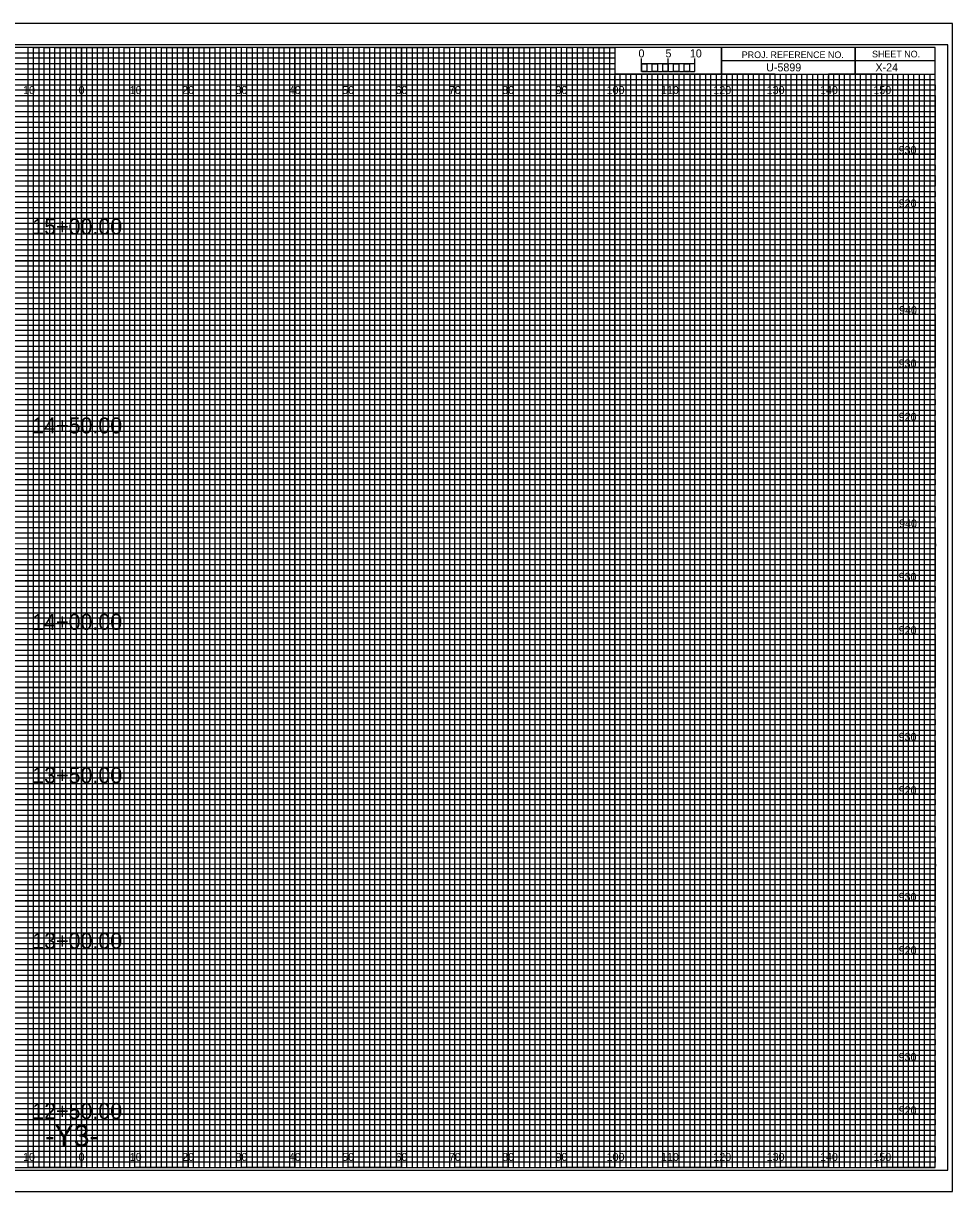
# Model space of a CAD drawing. Extents: x -13 to 323, y 216 to 434.
# Drawn here: x 149.1 to 323.3, y 215.5 to 434.5 of the extents above; entities that cross this region are included whole.
import ezdxf

# ---------------------------------------------------------------- set-up
doc = ezdxf.new("R2010")
doc.units = 0
for name, color, linetype in [('Prop XS Alignment Label', 7, 'Continuous'), ('Prop XS Bar Scale Labels', 7, 'Continuous'), ('Prop XS Elevation Labels', 7, 'Continuous'), ('Prop XS Label Text', 7, 'Continuous'), ('Prop XS Project Number', 7, 'Continuous'), ('Prop XS Shear Point Element', 7, 'Continuous'), ('Prop XS Shear Point Label', 7, 'Continuous'), ('Prop XS Sheet Number', 7, 'Continuous'), ('Prop XS Station Labels', 7, 'Continuous'), ('Scratch_Level_1', 7, 'Continuous'), ('Scratch_Level_4', 7, 'Continuous'), ('Sheet Cross Section Grid Minor 2 CELL', 7, 'Continuous'), ('Sheet Cross Section Scale CELL', 7, 'Continuous'), ('Sheet Cutting Line CELL', 7, 'Continuous'), ('Sheet DOT Grid CELL', 7, 'Continuous'), ('Sheet Plot Border Inside CELL', 7, 'Continuous'), ('Sheet Plot Border Outside CELL', 7, 'Continuous')]:
    doc.layers.add(name, color=color, linetype=linetype)

msp = doc.modelspace()

# ---------------------------------------------------------------- linework, layer by layer
at = {"layer": 'Prop XS Label Text'}
for points in [[(145, 220), (155, 220), (155, 430), (165, 430), (165, 220), (175, 220), (175, 430), (185, 430), (185, 220), (195, 220), (195, 430), (205, 430), (205, 220), (215, 220), (215, 430), (225, 430), (225, 220), (235, 220), (235, 430), (245, 430), (245, 220), (255, 220), (255, 430), (259.93, 430), (260, 430), (260, 425), (264.99, 425), (264.99, 220), (275, 220), (275, 425), (285, 425), (285, 220), (295, 220), (295, 425), (305, 425), (305, 220), (315, 220), (315, 425)], [(0, 425), (275, 425)], [(0, 405), (320, 405), (320, 415), (0, 415)], [(0, 385), (320, 385), (320, 395), (0, 395)], [(0, 365), (320, 365), (320, 375), (0, 375)], [(0, 345), (320, 345), (320, 355), (0, 355)], [(0, 325), (320, 325), (320, 335), (0, 335)], [(0, 305), (320, 305), (320, 315), (0, 315)], [(0, 285), (320, 285), (320, 295), (0, 295)], [(0, 265), (320, 265), (320, 275), (0, 275)], [(0, 245), (320, 245), (320, 255), (0, 255)], [(0, 225), (320, 225), (320, 235), (0, 235)]]:
    msp.add_lwpolyline(points, dxfattribs=at)
at = {"layer": 'Prop XS Shear Point Element'}
for p, q in [((305, 430), (305, 425)), ((305, 425), (305, 430)), ((280, 427.5), (280, 425)), ((320, 427.49), (280, 427.49)), ((280, 425), (320, 425))]:
    msp.add_line(p, q, dxfattribs=at)
for points in [[(320, 430), (0, 430), (0, 220), (320, 220)], [(280, 430), (260, 430), (260, 425.03), (280, 425.03)], [(320, 430), (280, 430), (280, 425), (320, 425)]]:
    msp.add_lwpolyline(points, close=True, dxfattribs=at)
at = {"layer": 'Prop XS Shear Point Label'}
for p, q in [((0, 429), (260, 429)), ((260, 427.98), (0, 427.98)), ((260, 429), (260, 427.98)), ((0, 427), (260, 427)), ((260, 425.89), (0, 425.89)), ((260, 427), (260, 425.89)), ((0, 424), (320, 424))]:
    msp.add_line(p, q, dxfattribs=at)
for points in [[(0, 423), (270, 423), (320, 423), (320, 422), (0, 422)], [(0, 421), (320, 421), (320, 419), (0, 419)], [(0, 418), (320, 418), (320, 417), (0, 416.98)], [(0, 416), (320, 416), (320, 414), (0, 414)], [(0, 413), (320, 413), (320, 412), (0, 412)], [(0, 411), (320, 411), (320, 409), (0, 409)], [(0, 408), (320, 408), (320, 407), (0, 407)], [(0, 406), (320, 406), (320, 404), (0, 404)], [(0, 403), (320, 403), (320, 402), (0, 402)], [(0, 401), (320, 401), (320, 399), (0, 399)], [(0, 398), (320, 398), (320, 397), (0, 397)], [(0, 396), (320, 396), (320, 393.95), (320, 393), (320, 392), (0, 392)], [(0, 394), (320, 394), (320, 393), (0, 393)], [(0, 391), (320, 391), (320, 389), (0, 389.03)], [(0, 389.03), (320, 389), (320, 388), (0, 388)], [(0, 387), (320, 387), (320, 386), (0, 386)], [(0, 384), (320, 384), (320, 383), (0, 383)], [(0, 382), (320, 382), (320, 381), (0, 381)], [(-0.07, 378.89), (320, 378.89), (320, 377.88), (-0.07, 377.88)], [(0, 377), (320, 377), (320, 376), (0, 376)], [(0, 374), (320, 374), (320, 373), (0, 373)], [(0, 372), (320, 372), (320, 371), (0, 371)], [(0, 369), (320, 369), (320, 368), (0, 368)], [(0, 367), (320, 367), (320, 366), (0, 366)], [(0, 364), (320, 364), (320, 363), (0, 363)], [(0, 362), (320, 362), (320, 361), (0, 361)], [(0, 359), (320, 359), (319.99, 357.98), (0, 358)], [(0, 357), (320, 357), (320, 356), (0, 356)], [(0, 354), (320, 354), (320, 353), (0, 353)], [(0, 352), (320, 352), (320, 351), (0, 351)], [(0, 349), (320, 349), (320, 348), (0, 348)], [(0, 347), (320, 347), (320, 346), (0, 346)], [(0, 344), (320, 344), (320, 343), (0, 343)], [(0, 342), (320, 342), (320, 341), (0, 341)], [(0, 339), (320, 339), (320, 338), (0, 338)], [(0, 336.99), (320.07, 336.91), (320, 336), (0, 336)], [(0, 334), (320, 334), (320, 333), (0, 333)], [(0, 332), (320, 332), (320, 331), (0, 331)], [(0, 329), (320, 329), (320, 328), (0, 328)], [(0, 327), (320, 327), (320, 326), (0, 326)], [(0, 324), (320, 324), (320, 323), (0, 323)], [(0, 322), (320, 322), (320, 321), (0, 321)], [(0, 319), (320, 319), (320, 318), (0, 318)], [(0, 317), (320, 317), (320, 316), (0, 316)], [(0, 314), (320, 314), (320, 313), (0, 313)], [(0, 312), (320, 312), (320, 311), (0, 311)], [(0, 309), (320, 309), (320, 308), (0, 308)], [(0, 307), (320, 307), (320, 306), (0, 306)], [(0, 304), (320, 304), (320, 303), (0, 303)], [(0, 302), (320, 302), (320, 301), (0, 301)], [(0, 299), (320, 299), (319.99, 297.98), (0, 298)], [(0, 297), (320, 297), (320, 296), (0, 296)], [(0, 294), (320, 294), (320, 293), (0, 293)], [(0, 292), (320, 292), (320, 291), (0, 291)], [(0, 289), (320, 289), (320, 288), (0, 288)], [(0, 287), (320, 287), (320, 286), (0, 286)], [(0, 284), (320, 284), (320, 283), (0, 283)], [(0, 282), (320, 282), (320, 281), (0, 281)], [(0, 279), (320, 279), (320, 278), (0, 278)], [(0, 276.99), (320.07, 276.91), (320, 276), (0, 276)], [(0, 274), (320, 274), (320, 273), (0, 273)], [(0, 272), (320, 272), (320, 271), (0, 271)], [(0, 269), (320, 269), (320, 268), (0, 268)], [(0, 267), (320, 267), (320, 266), (0, 266)], [(0, 264), (320, 264), (320, 263), (0, 263)], [(0, 262), (320, 262), (320, 261), (0, 261)], [(0, 259), (320, 259), (320, 258), (0, 258)], [(0, 257), (320, 257), (320, 256), (0, 256)], [(0, 254), (320, 254), (320, 253), (0, 253)], [(0, 252), (320, 252), (320, 251), (0, 251)], [(0, 249), (320, 249), (320, 248), (0, 248)], [(0, 247), (320, 247), (320, 246), (0, 246)], [(0, 244), (320, 244), (320, 243), (0, 243)], [(0, 242), (320, 242), (320, 241), (0, 241)], [(0, 239), (320, 239), (320, 238), (0, 238)], [(0, 237), (320, 237), (320, 236), (0, 236)], [(0, 234), (320, 234), (320, 233), (0, 233)], [(0, 232), (320, 232), (320, 231), (0, 231)], [(0, 229), (320, 229), (320, 228), (0, 228)], [(0, 227), (320, 227), (320, 226), (0, 226)], [(0, 224), (320, 224), (320, 223), (0, 223)], [(0, 222), (320, 222), (320, 221), (0, 221)]]:
    msp.add_lwpolyline(points, dxfattribs=at)
at = {"layer": 'Scratch_Level_4'}
for p, q in [((150, 430), (140, 430)), ((150, 220), (150, 430)), ((170, 430), (160, 430)), ((160, 430), (160, 220)), ((170, 220), (170, 430)), ((190, 430), (180, 430)), ((180, 430), (180, 220)), ((190, 220), (190, 430)), ((210, 430), (200, 430)), ((200, 430), (200, 220)), ((210, 220), (210, 430)), ((230, 430), (220, 430)), ((220, 430), (220, 220)), ((230, 220), (230, 430)), ((250, 430), (240, 430)), ((240, 430), (240, 220)), ((250, 220), (250, 430)), ((260, 430), (260, 220)), ((270, 220), (270, 425)), ((290, 425), (280, 425)), ((280, 425), (280, 220)), ((290, 220), (290, 425)), ((310, 425), (300, 425)), ((300, 425), (300, 220)), ((310, 220), (310, 425)), ((160, 220), (150, 220)), ((180, 220), (170, 220)), ((200, 220), (190, 220)), ((220, 220), (210, 220)), ((240, 220), (230, 220)), ((260, 220), (250, 220)), ((280, 220), (270, 220)), ((300, 220), (290, 220)), ((320, 220), (310, 220)), ((320, 220), (320, 220))]:
    msp.add_line(p, q, dxfattribs=at)
for points in [[(0, 420), (320, 420), (320, 410), (0, 410)], [(0, 400), (320, 400), (320, 390), (0, 390)], [(0, 380), (320, 380), (320, 370), (0, 370)], [(0, 360), (320, 360), (320, 350), (0, 350)], [(0, 340), (320, 340), (320, 330), (0, 330)], [(0, 320), (320, 320), (320, 310), (0, 310)], [(0, 300), (320, 300), (320, 290), (0, 290)], [(0, 280), (320, 280), (320, 270), (0, 270)], [(0, 260), (320, 260), (320, 250), (0, 250)], [(0, 240), (320, 240), (320, 230), (0, 230)]]:
    msp.add_lwpolyline(points, dxfattribs=at)
at = {"layer": 'Sheet Cross Section Grid Minor 2 CELL'}
for p, q in [((267, 425), (266.01, 425)), ((266.01, 425), (266.01, 220)), ((267, 220), (267, 425)), ((269, 425), (268, 425)), ((268, 425), (268, 220)), ((269, 220), (269, 425)), ((266.01, 220), (265, 220)), ((268, 220), (267, 220))]:
    msp.add_line(p, q, dxfattribs=at)
for points in [[(150, 220), (151, 220), (151, 430), (152, 430), (152, 220)], [(152, 220), (153, 220), (153, 430), (154, 430), (154, 220)], [(155, 220), (156, 220), (156, 430), (157, 430), (157, 220)], [(157, 220), (158, 220), (158, 430), (159, 430), (159, 220)], [(160, 220), (161, 220), (161, 430), (162, 430), (162, 220)], [(162, 220), (163, 220), (163, 430), (164, 430), (164, 220)], [(165, 220), (166, 220), (166, 430), (167, 430), (167, 220)], [(167, 220), (168, 220), (168, 430), (169, 430), (169, 220)], [(170, 220), (171, 220), (171, 430), (172, 430), (172, 220)], [(172, 220), (173, 220), (173, 430), (174, 430), (174, 220)], [(175, 220), (176, 220), (176, 430), (177, 430), (177, 220)], [(177, 220), (178, 220), (178, 430), (179, 430), (179, 220)], [(180, 220), (181, 220), (181, 430), (182, 430), (182, 220)], [(182, 220), (183, 220), (183, 430), (184, 430), (184, 220)], [(185, 220), (186, 220), (186, 430), (187, 430), (187, 220)], [(187, 220), (188, 220), (188, 430), (189, 430), (189, 220)], [(190, 220), (191, 220), (191, 430), (192, 430), (192, 220)], [(192, 220), (193, 220), (193, 430), (194, 430), (194, 220)], [(195, 220), (196, 220), (196, 430), (197, 430), (197, 220)], [(197, 220), (198, 220), (198, 430), (199, 430), (199, 220)], [(200, 220), (201, 220), (201, 430), (202, 430), (202, 220)], [(202, 220), (203, 220), (203, 430), (204, 430), (204, 220)], [(205, 220), (206, 220), (206, 430), (207, 430), (207, 220)], [(207, 220), (208, 220), (208, 430), (209, 430), (209, 220)], [(210, 220), (211, 220), (211, 430), (212, 430), (212, 220)], [(212, 220), (213, 220), (213, 430), (214, 430), (214, 220)], [(215, 220), (216, 220), (216, 430), (217, 430), (217, 220)], [(217, 220), (218, 220), (218, 430), (219, 430), (219, 220)], [(220, 220), (221, 220), (221, 430), (222, 430), (222, 220)], [(222, 220), (223, 220), (223, 430), (224, 430), (224, 220)], [(225, 220), (226, 220), (226, 430), (227, 430), (227, 220)], [(227, 220), (228, 220), (228, 430), (229, 430), (229, 220)], [(230, 220), (231, 220), (231, 430), (232, 430), (232, 220)], [(232, 220), (233, 220), (233, 430), (234, 430), (234, 220)], [(235, 220), (236, 220), (236, 430), (237, 430), (237, 220)], [(237, 220), (238, 220), (238, 430), (239, 430), (239, 220)], [(240, 220), (241, 220), (241, 430), (242, 430), (242, 220)], [(242, 220), (243, 220), (243, 430), (244, 430), (244, 220)], [(245, 220), (246, 220), (246, 430), (247, 430), (247, 220)], [(247, 220), (248, 220), (248, 430), (249, 430), (249, 220)], [(250, 220), (251, 220), (251, 430), (252, 430), (252, 220)], [(252, 220), (253, 220), (253, 430), (254, 430), (254, 220)], [(255, 220), (256, 220), (256, 430), (257, 430), (257, 220)], [(257, 220), (258, 220), (258, 430), (259, 430), (259, 220)], [(260, 220), (261, 220), (261, 425), (262.02, 425), (262.02, 220)], [(262, 220), (263, 220), (263, 425), (263.99, 425), (263.99, 220)], [(270, 220), (270.98, 220), (270.98, 425), (272, 425), (272, 220)], [(272, 220), (273, 220), (273, 425), (274.05, 425), (274.05, 220)], [(275, 220), (276, 220), (276, 425), (277, 425), (277, 220)], [(277, 220), (278, 220), (278, 425), (279, 425), (279, 220)], [(280, 220), (281, 220), (281, 425), (282, 425), (282, 220)], [(282, 220), (283, 220), (283, 425), (284, 425), (284, 220)], [(285, 220), (286, 220), (286, 425), (287, 425), (287, 220)], [(287, 220), (288, 220), (288, 425), (289, 425), (289, 220)], [(290, 220), (291, 220), (291, 425), (292, 425), (292, 220)], [(292, 220), (293, 220), (293, 425), (294, 425), (294, 220)], [(295, 220), (296, 220), (296, 425), (297, 425), (297, 220)], [(297, 220), (298, 220), (298, 425), (299, 425), (299, 220)], [(300, 220), (301, 220), (301, 425), (302, 425), (302, 220)], [(302, 220), (303, 220), (303, 425), (304, 425), (304, 220)], [(305, 220), (306, 220), (306, 425), (307, 425), (307, 220)], [(307, 220), (308, 220), (308, 425), (309, 425), (309, 220)], [(310, 220), (311, 220), (311, 425), (312, 425), (312, 220)], [(312, 220), (313, 220), (313, 425), (314, 425), (314, 220)], [(315, 220), (316, 220), (316, 425), (317, 425), (317, 220)], [(317, 220), (318, 220), (318, 425), (319, 425), (319, 220)]]:
    msp.add_lwpolyline(points, dxfattribs=at)
at = {"layer": 'Sheet Cross Section Scale CELL'}
for p, q in [((265, 425.49), (265, 427.9)), ((265, 426.9), (265, 427.9)), ((270, 425.49), (270, 427.9)), ((275, 425.49), (275, 427.9)), ((275, 426.9), (275, 427.9))]:
    msp.add_line(p, q, dxfattribs=at)
for points in [[(275, 426.9), (265, 426.9), (265, 425.49), (275, 425.49)], [(265, 426.9), (266, 426.9), (266, 425.49), (265, 425.49)], [(267, 426.9), (268, 426.9), (268, 425.49), (267, 425.49)], [(269, 426.9), (270, 426.9), (270, 425.49), (269, 425.49)], [(271, 426.9), (272, 426.9), (272, 425.49), (271, 425.49)], [(273, 426.9), (274, 426.9), (274, 425.49), (273, 425.49)]]:
    msp.add_lwpolyline(points, close=True, dxfattribs=at)
at = {"layer": 'Sheet Cutting Line CELL'}
for p, q in [((323.3, 434.5), (-13.4, 434.5)), ((-13.4, 215.5), (323.3, 215.5))]:
    msp.add_line(p, q, dxfattribs=at)
at = {"layer": 'Sheet DOT Grid CELL'}
for p, q in [((150, 220), (150, 430)), ((160, 220), (160, 430)), ((170, 220), (170, 430)), ((180, 220), (180, 430)), ((190, 220), (190, 430)), ((200, 220), (200, 430)), ((210, 220), (210, 430)), ((220, 220), (220, 430)), ((230, 220), (230, 430)), ((240, 220), (240, 430)), ((250, 220), (250, 430)), ((260, 220), (260, 424.69)), ((270, 220), (270, 424.69)), ((280, 220), (280, 424.69)), ((290, 220), (290, 424.69)), ((300, 220), (300, 424.69)), ((310, 220), (310, 424.69)), ((0, 420), (320, 420)), ((0, 410), (320, 410)), ((0, 400), (320, 400)), ((0, 390), (320, 390)), ((0, 380), (320, 380)), ((0, 370), (320, 370)), ((0, 360), (320, 360)), ((0, 350), (320, 350)), ((0, 340), (320, 340)), ((0, 330), (320, 330)), ((0, 320), (320, 320)), ((0, 310), (320, 310)), ((0, 300), (320, 300)), ((0, 290), (320, 290)), ((0, 280), (320, 280)), ((0, 270), (320, 270)), ((0, 260), (320, 260)), ((0, 250), (320, 250)), ((0, 240), (320, 240)), ((0, 230), (320, 230))]:
    msp.add_line(p, q, dxfattribs=at)
at = {"layer": 'Sheet Plot Border Inside CELL'}
msp.add_lwpolyline([(-10.8, 219.5), (322.4, 219.5), (322.4, 430.5), (-10.8, 430.5)], close=True, dxfattribs=at)
at = {"layer": 'Sheet Plot Border Outside CELL'}
msp.add_lwpolyline([(-13.4, 215.5), (323.3, 215.5), (323.3, 434.5), (-13.4, 434.5)], close=True, dxfattribs=at)

# ---------------------------------------------------------------- texts
at = {"layer": 'Prop XS Alignment Label'}
msp.add_text('-Y3-', height=4, dxfattribs=at).set_placement((153.17, 224))
at = {"layer": 'Prop XS Bar Scale Labels'}
for s, p in [('5', (269.47, 428.12)), ('10', (274.04, 428.12))]:
    msp.add_text(s, height=1.5, dxfattribs=at).set_placement(p)
at = {"layer": 'Prop XS Elevation Labels'}
for s, p in [('930', (313.18, 410)), ('920', (313.19, 400)), ('940', (313.26, 380)), ('930', (313.18, 370)), ('920', (313.19, 360)), ('940', (313.26, 340)), ('930', (313.18, 330)), ('920', (313.19, 320)), ('930', (313.18, 300)), ('920', (313.19, 290)), ('930', (313.18, 270)), ('920', (313.19, 260)), ('930', (313.18, 240)), ('920', (313.19, 230))]:
    msp.add_text(s, height=1.5, dxfattribs=at).set_placement(p)
at = {"layer": 'Prop XS Project Number'}
msp.add_text('U-5899', height=1.5, dxfattribs=at).set_placement((288.34, 425.5))
at = {"layer": 'Prop XS Shear Point Element'}
for s, p in [('PROJ. REFERENCE NO.', (283.77, 427.99)), ('SHEET NO.', (308.19, 428.12))]:
    msp.add_text(s, height=1.25, dxfattribs=at).set_placement(p)
at = {"layer": 'Prop XS Sheet Number'}
msp.add_text('X-24', height=1.5, dxfattribs=at).set_placement((308.83, 425.5))
at = {"layer": 'Prop XS Station Labels'}
for s, p in [('15+00.00', (150.77, 394.92)), ('14+50.00', (150.77, 357.63)), ('14+00.00', (150.77, 320.81)), ('13+50.00', (150.77, 292.07)), ('13+00.00', (150.77, 261.03)), ('12+50.00', (150.77, 229.11))]:
    msp.add_text(s, height=3, dxfattribs=at).set_placement(p)
at = {"layer": 'Scratch_Level_1'}
for s, p in [('10', (149.04, 421.25)), ('0', (159.45, 421.25)), ('0', (159.45, 421.25)), ('10', (169.04, 421.25)), ('20', (178.86, 421.25)), ('30', (188.86, 421.25)), ('40', (198.86, 421.25)), ('50', (208.86, 421.25)), ('60', (218.86, 421.25)), ('70', (228.86, 421.25)), ('80', (238.86, 421.25)), ('90', (248.86, 421.25)), ('100', (258.44, 421.25)), ('110', (268.62, 421.25)), ('120', (278.44, 421.25)), ('130', (288.44, 421.25)), ('140', (298.44, 421.25)), ('150', (308.44, 421.25)), ('10', (149.04, 221.25)), ('0', (159.45, 221.25)), ('0', (159.45, 221.25)), ('10', (169.04, 221.25)), ('20', (178.86, 221.25)), ('30', (188.86, 221.25)), ('40', (198.86, 221.25)), ('50', (208.86, 221.25)), ('60', (218.86, 221.25)), ('70', (228.86, 221.25)), ('80', (238.86, 221.25)), ('90', (248.86, 221.25)), ('100', (258.44, 221.25)), ('110', (268.62, 221.25)), ('120', (278.44, 221.25)), ('130', (288.44, 221.25)), ('140', (298.44, 221.25)), ('150', (308.44, 221.25))]:
    msp.add_text(s, height=1.5, dxfattribs=at).set_placement(p)
at = {"layer": 'Sheet Cross Section Scale CELL'}
msp.add_text('0', height=1.5, dxfattribs=at).set_placement((264.41, 428.12))

doc.saveas('drawing.dxf')
